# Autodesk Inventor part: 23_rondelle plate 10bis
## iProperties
Shininess: 20.0
Length Units: 11270
Angle Units: 11279
Time Units: 11290
Mass Units: 11283
Length Display Precision: 3
Angle Display Precision: 2
Created: 2000-10
Part Number: 23_rondelle plate 10bis
Material: Par défaut
Document SubType Name: Modélisation
Density: 0.0
Volumn: 0.0
Area: 0.0
PropertySet Name: Model Information
Control State: 0
Master: False
Checked Out: False
Author: Laurent GAUTHERON
